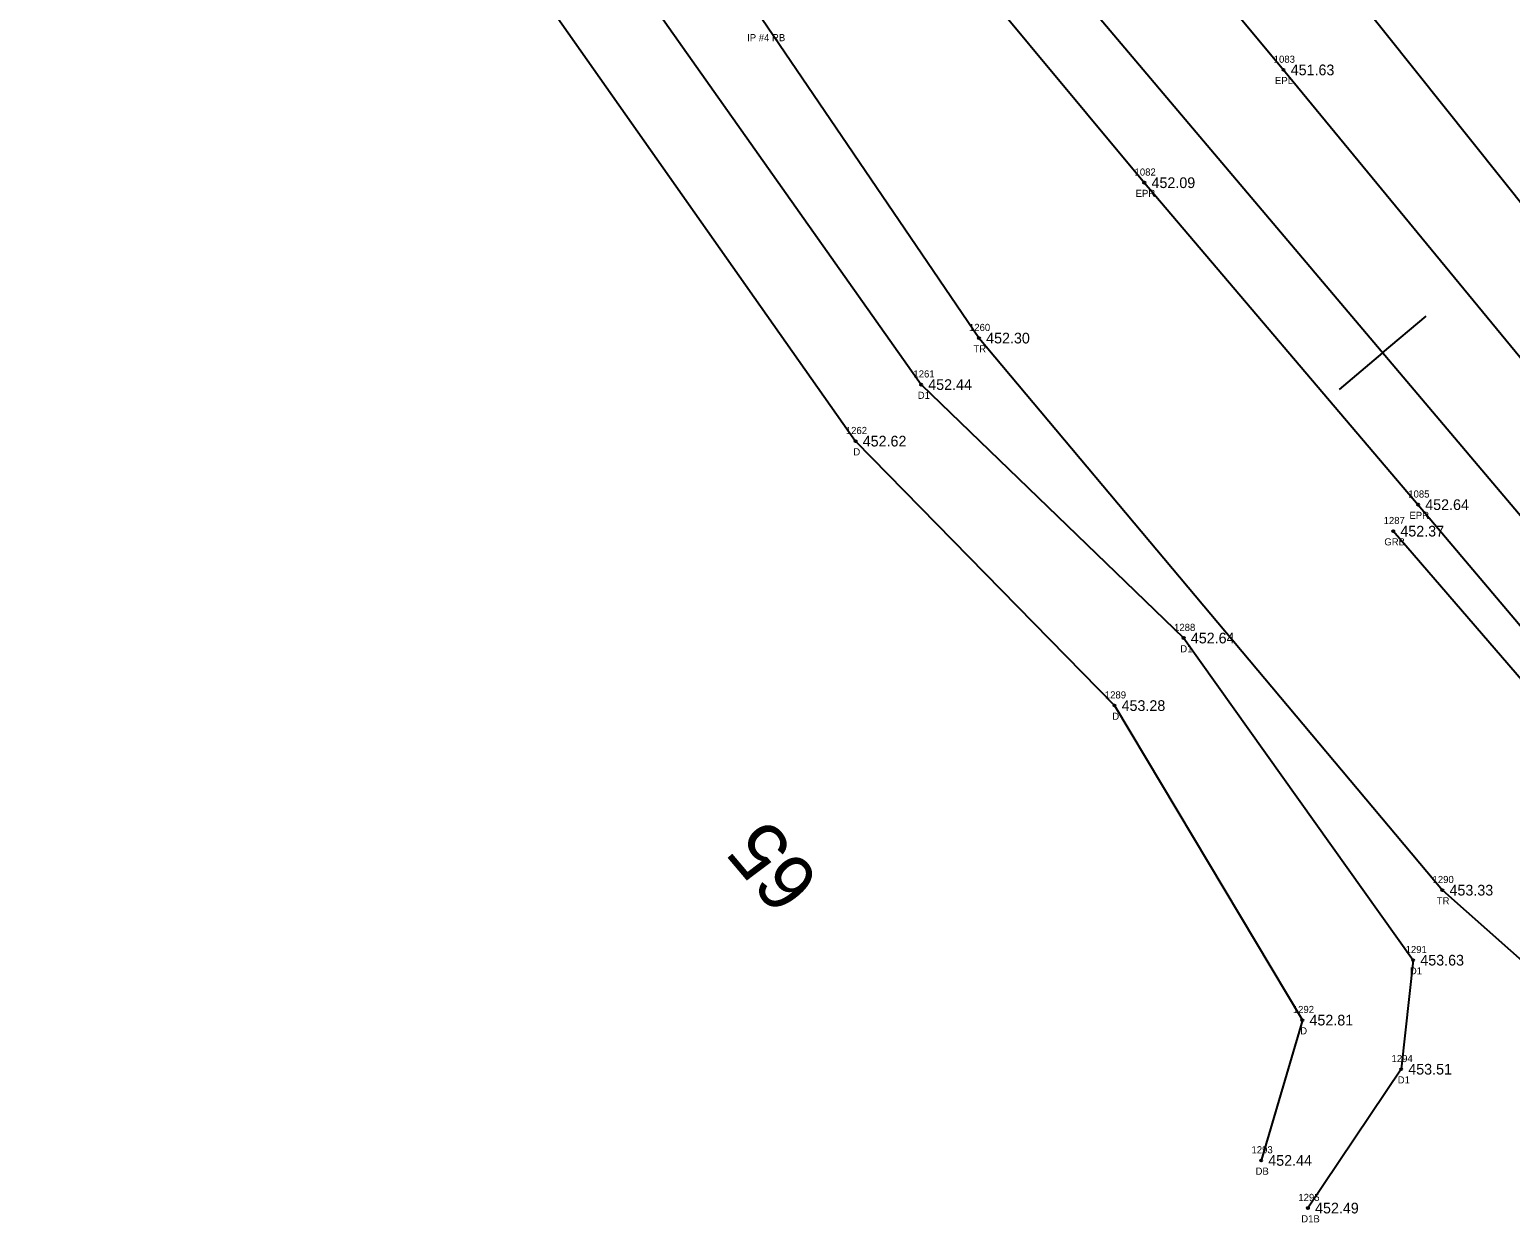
# Model space of a CAD drawing. Extents: x 1745838 to 1751416, y 649214 to 655806.
# Drawn here: x 1748785.5 to 1748993.4, y 651485.9 to 651653.4 of the extents above; entities that cross this region are included whole.
import ezdxf

# ---------------------------------------------------------------- set-up
doc = ezdxf.new("R2010")
doc.units = 0
for name, color, linetype in [('RD_EX_Driveway', 7, 'Continuous'), ('RD_EX_Driveway_txCode', 7, 'Continuous'), ('RD_EX_DV_Prop_txCode', 7, 'Continuous'), ('RD_EX_Fence_Other', 7, 'Continuous'), ('RD_EX_GuardRail', 7, 'Continuous'), ('RD_EX_GuardRail_txCode', 7, 'Continuous'), ('RD_EX_Road', 7, 'Continuous'), ('RD_EX_Road_txCode', 7, 'Continuous'), ('RD_EX_TX_Driveway_ELEV', 7, 'Continuous'), ('RD_EX_TX_GuardRail_ELEV', 7, 'Continuous'), ('RD_EX_TX_Road_ELEV', 7, 'Continuous'), ('RD_EX_TX_VEG_ELEV', 7, 'Continuous'), ('RD_EX_VEG', 7, 'Continuous'), ('RD_EX_VEG_txCode', 7, 'Continuous'), ('RD_HC_Cl', 7, 'Continuous'), ('RD_HC_Data_Tic', 7, 'Continuous'), ('RD_HC_TX_Sta50', 7, 'Continuous'), ('RD_SMD_Locator', 7, 'Continuous')]:
    doc.layers.add(name, color=color, linetype=linetype)

msp = doc.modelspace()

# ---------------------------------------------------------------- linework, layer by layer
at = {"layer": 'RD_EX_Driveway'}
for points in [[(1748795.77, 651766.01), (1748801.61, 651745.83), (1748812.74, 651721.07), (1748842.07, 651680), (1748901.43, 651595.63), (1748937.78, 651558.5), (1748964.16, 651514.33), (1748958.37, 651494.63)], [(1748807.66, 651765.37), (1748813.42, 651752.22), (1748822.99, 651728.69), (1748851.31, 651687.61), (1748910.63, 651603.57), (1748947.5, 651567.98), (1748979.72, 651522.75), (1748978.03, 651507.44), (1748964.94, 651487.94)]]:
    msp.add_lwpolyline(points, dxfattribs=at)
at = {"layer": 'RD_EX_Fence_Other'}
msp.add_lwpolyline([(1748731.62, 652100.81), (1748735.3, 652085.13), (1748740.66, 652074.74), (1748752.07, 652055.81), (1748751.12, 652043.36), (1748750.95, 652030.95), (1748767.27, 651998.87), (1748767.27, 651998.87), (1748762.01, 651980.2), (1748768.15, 651939.38), (1748794.06, 651893.44), (1748822.68, 651853.02), (1748850.01, 651816.55), (1748881.26, 651774.66), (1748911.24, 651735.35), (1748972.04, 651657.73), (1749035.87, 651577.68), (1749083.16, 651517.4), (1749096.96, 651526.43)], dxfattribs=at)
at = {"layer": 'RD_EX_GuardRail'}
msp.add_lwpolyline([(1749041.61, 651506.8), (1749004.67, 651550.83), (1748976.92, 651582.99)], dxfattribs=at)
at = {"layer": 'RD_EX_Road'}
for points in [[(1748430.72, 652573.59), (1748472.3, 652485.07), (1748515.54, 652394.24), (1748548.4, 652323.99), (1748589.23, 652237.29), (1748607.12, 652198.86), (1748609.09, 652199.5), (1748633.39, 652147.73), (1748655.85, 652100.41), (1748677.16, 652057.64), (1748701.06, 652012.63), (1748725.12, 651970.47), (1748751.23, 651927.26), (1748777.84, 651886.08), (1748807.14, 651843.17), (1748836.63, 651802.6), (1748866.26, 651763.37), (1748897.62, 651724.52), (1748961.52, 651647.76), (1748997.97, 651603.49), (1749026.31, 651569.66), (1749088.99, 651495.68)], [(1748586.63, 652188.46), (1748610.53, 652136.78), (1748632.69, 652090.17), (1748654.96, 652046.55), (1748679.12, 652001.12), (1748703.77, 651957.47), (1748729.93, 651914.24), (1748757.13, 651872.56), (1748787.32, 651828.58), (1748802.29, 651807.16), (1748814.23, 651790.24), (1748816.48, 651787.94), (1748845.7, 651749.02), (1748877.33, 651709.65), (1748941.98, 651631.92), (1748980.41, 651586.71), (1749008.3, 651553.67), (1749070.58, 651479.58), (1749079.79, 651486.92), (1749088.99, 651495.68)]]:
    msp.add_lwpolyline(points, dxfattribs=at)
at = {"layer": 'RD_EX_VEG'}
for points in [[(1748727.21, 652033.07), (1748719.78, 652021.13), (1748741.73, 651976.11), (1748768.15, 651939.38), (1748794.06, 651893.44), (1748822.68, 651853.02), (1748850.01, 651816.55), (1748881.26, 651774.66), (1748911.24, 651735.35), (1748972.04, 651657.73), (1749035.87, 651577.68), (1749102.17, 651496.37), (1749126.54, 651516.47), (1749148.35, 651529.92), (1749165.73, 651545.44)], [(1748821.95, 651746.88), (1748830.05, 651733.37), (1748861.03, 651695.08), (1748918.76, 651610.1), (1748983.82, 651532.58), (1749046.48, 651476.99), (1749050.27, 651445.74), (1749011.3, 651414.42)]]:
    msp.add_lwpolyline(points, dxfattribs=at)
at = {"layer": 'RD_HC_Cl'}
msp.add_line((1749546.44, 650932.91), (1748908.1, 651687.62), dxfattribs=at)
at = {"layer": 'RD_HC_Data_Tic'}
for q in [(1748981.53, 651613.19), (1748969.31, 651602.86)]:
    msp.add_line((1748975.42, 651608.03), q, dxfattribs=at)
at = {"layer": 'RD_SMD_Locator'}
for centre in [(1748961.52, 651647.76), (1748941.98, 651631.92), (1748918.76, 651610.1), (1748910.63, 651603.57), (1748901.43, 651595.63), (1748980.41, 651586.71), (1748976.92, 651582.99), (1748947.5, 651567.98), (1748937.78, 651558.5), (1748983.82, 651532.58), (1748979.72, 651522.75), (1748964.16, 651514.33), (1748978.03, 651507.44), (1748958.37, 651494.63), (1748964.94, 651487.94)]:
    msp.add_circle(centre, 0.15, dxfattribs=at)

# ---------------------------------------------------------------- texts
at = {"layer": 'RD_EX_Driveway_txCode'}
for s, p in [('1261', (1748909.55, 651604.57)), ('D1', (1748910.16, 651601.57)), ('1262', (1748900.06, 651596.63)), ('D', (1748901.12, 651593.63)), ('1288', (1748946.15, 651568.98)), ('D1', (1748947.02, 651565.98)), ('1289', (1748936.43, 651559.5)), ('D', (1748937.47, 651556.5)), ('1291', (1748978.66, 651523.75)), ('D1', (1748979.25, 651520.75)), ('1292', (1748962.82, 651515.33)), ('D', (1748963.86, 651512.33)), ('1294', (1748976.68, 651508.44)), ('D1', (1748977.55, 651505.44)), ('1293', (1748957.02, 651495.63)), ('DB', (1748957.59, 651492.63)), ('1295', (1748963.6, 651488.94)), ('D1B', (1748964, 651485.94))]:
    msp.add_text(s, height=1, dxfattribs=at).set_placement(p)
at = {"layer": 'RD_EX_DV_Prop_txCode'}
msp.add_text('IP #4 RB', height=1, dxfattribs=at).set_placement((1748886.2, 651651.79))
at = {"layer": 'RD_EX_GuardRail_txCode'}
for s, p in [('1287', (1748975.57, 651583.99)), ('GRB', (1748975.67, 651580.99))]:
    msp.add_text(s, height=1, dxfattribs=at).set_placement(p)
at = {"layer": 'RD_EX_Road_txCode'}
for s, p in [('1083', (1748960.14, 651648.76)), ('EPL', (1748960.32, 651645.76)), ('1082', (1748940.6, 651632.92)), ('EPR', (1748940.75, 651629.92)), ('1085', (1748979.03, 651587.71)), ('EPR', (1748979.19, 651584.71))]:
    msp.add_text(s, height=1, dxfattribs=at).set_placement(p)
at = {"layer": 'RD_EX_TX_Driveway_ELEV'}
for s, p in [('452.44', (1748911.63, 651602.82)), ('452.62', (1748902.43, 651594.88)), ('452.64', (1748948.5, 651567.23)), ('453.28', (1748938.78, 651557.75)), ('453.63', (1748980.72, 651522)), ('452.81', (1748965.16, 651513.58)), ('453.51', (1748979.03, 651506.69)), ('452.44', (1748959.37, 651493.88)), ('452.49', (1748965.94, 651487.19))]:
    msp.add_text(s, height=1.5, dxfattribs=at).set_placement(p)
at = {"layer": 'RD_EX_TX_GuardRail_ELEV'}
msp.add_text('452.37', height=1.5, dxfattribs=at).set_placement((1748977.92, 651582.24))
at = {"layer": 'RD_EX_TX_Road_ELEV'}
for s, p in [('451.63', (1748962.52, 651647.01)), ('452.09', (1748942.98, 651631.17)), ('452.64', (1748981.41, 651585.96))]:
    msp.add_text(s, height=1.5, dxfattribs=at).set_placement(p)
at = {"layer": 'RD_EX_TX_VEG_ELEV'}
for s, p in [('452.30', (1748919.76, 651609.35)), ('453.33', (1748984.82, 651531.83))]:
    msp.add_text(s, height=1.5, dxfattribs=at).set_placement(p)
at = {"layer": 'RD_EX_VEG_txCode'}
for s, p in [('1260', (1748917.35, 651611.1)), ('TR', (1748917.97, 651608.1)), ('1290', (1748982.44, 651533.58)), ('TR', (1748983.03, 651530.58))]:
    msp.add_text(s, height=1, dxfattribs=at).set_placement(p)
at = {"layer": 'RD_HC_TX_Sta50'}
msp.add_text('65', height=8, rotation=130.2248, dxfattribs=at).set_placement((1748896.68, 651533.88))

doc.saveas('drawing.dxf')
